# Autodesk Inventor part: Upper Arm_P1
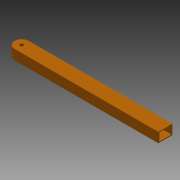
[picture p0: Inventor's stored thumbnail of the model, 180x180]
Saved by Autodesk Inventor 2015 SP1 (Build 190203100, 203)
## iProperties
Created: 2008-11
Part Number: Upper Arm_P1
Document SubType Name: Modeling
Designer: dwoollam
Density: 7.85 g/cm^3
Material: Steel
Appearance: Orange
Mass: 266166 g
Surface Area: 39951.1 cm^2
Volume: 33906.5 cm^3
Dwg_Category: Clearance_Mewp
INSTALLATION: False
CIVIL_WORK: False
EARTHING: False
MOUNTING: False
Author: dwoollam
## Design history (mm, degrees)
sketch "Sketch1"
  geometry: L1 (0, 122.5)-(2500, 122.5); L2 (0, -122.5)-(2500, -122.5); L3 (2500, -122.5)-(2500, 122.5); L4 (2500, 107.5)-(50, 107.5); L5 (50, 107.5)-(50, -107.5); L6 (50, -107.5)-(2500, -107.5); L7 (2500, -107.5)-(2500, 107.5); C1 r 30 at (0, 0); A1 r 122.5 centre (0, 0) between (0, 122.5) and (0, -122.5); 5 further points
  constraints: 14 end point, 5 coincident, 3 horizontal, 3 midpoint, 2 centre point, 2 point on circle, 2 tangent, 1 collinear, 1 horizontal alignment, 1 parallel, 1 perpendicular, 1 vertical alignment
  dimensions: "d0" = 60 diameter of C1; "d1" = 245 diameter of A1; "d2" = 2500 distance of L2.start L2.end; "d16" = 215 distance of L4.end L5.end; "d19" = 2450 distance between parallel lines of L3 L5
extrude "Main Arm" new body sketch "Sketch1" stored distance "d5" = 170; taper "d6" = 0 deg
extrude "Main Arm_Sub1" cut sketch "Sketch1" stored distance "d10" = 140; taper "d11" = 0 deg
body "Solid1"
